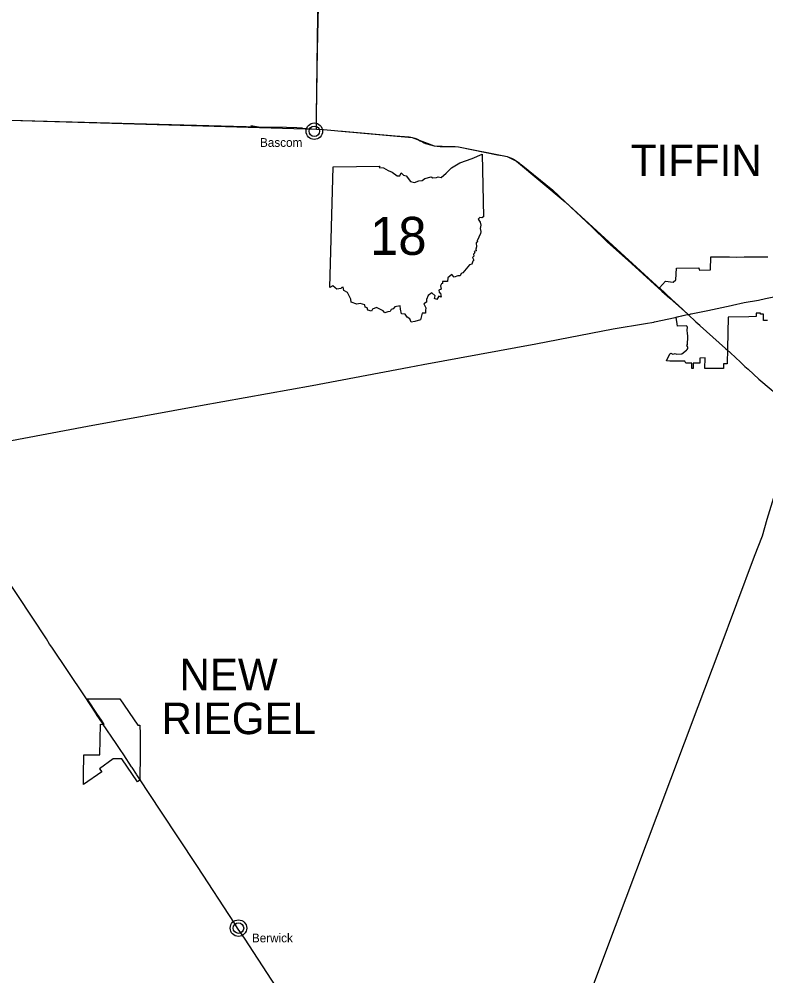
# Model space of a CAD drawing. Extents: x 0 to 882, y 0 to 440.
# Drawn here: x 198.3 to 287.2, y 123.7 to 237.6 of the extents above; entities that cross this region are included whole.
import ezdxf

# ---------------------------------------------------------------- set-up
doc = ezdxf.new("R2010")
doc.units = 0
for name, color, linetype in [('DV_X_Corp_Line', 7, 'Continuous'), ('GM_X_Corporation_Text', 7, 'Continuous'), ('GM_X_State_Route', 7, 'Continuous'), ('GM_X_US_Route', 7, 'Continuous'), ('PV_P_Text', 7, 'Continuous'), ('RD_P_Fence', 7, 'Continuous')]:
    doc.layers.add(name, color=color, linetype=linetype)

msp = doc.modelspace()

# ---------------------------------------------------------------- linework, layer by layer
at = {"layer": 'DV_X_Corp_Line'}
msp.add_lwpolyline([(287.43, 201.7), (286.94, 201.72), (286.95, 202.46), (286.58, 202.47), (286.58, 202.57), (286.46, 202.58), (286.08, 202.59), (286.07, 202.17), (285.19, 202.15), (282.76, 202.12), (282.67, 198.36), (282.62, 196.55), (282.2, 196.55), (282.19, 196), (281.61, 196), (279.98, 195.99), (280, 197.25), (279.37, 197.24), (279.37, 196.63), (278.59, 196.63), (278.59, 195.98), (278.44, 195.98), (278.44, 196.63), (277.82, 196.63), (277.7, 196.63), (277.6, 196.85), (275.8, 196.86), (275.39, 196.92), (275.81, 197.74), (275.93, 197.81), (276.17, 197.69), (276.3, 197.73), (276.43, 197.77), (276.59, 197.72), (277.24, 197.76), (277.79, 198.17), (277.86, 198.27), (277.94, 198.36), (277.96, 198.48), (277.9, 198.6), (277.84, 198.72), (277.89, 198.86), (277.93, 199.76), (277.93, 199.93), (277.9, 200.12), (277.87, 200.61), (277.9, 200.87), (277.88, 200.98), (277.82, 201.05), (277.79, 201.07), (276.73, 201.03), (276.55, 202.11), (277.71, 202.37), (277.97, 202.42), (276.84, 203.5), (276.04, 204.23), (274.57, 205.58), (275.3, 206.41), (276.18, 206.27), (276.5, 206.54), (276.58, 207.93), (279.25, 207.98), (279.24, 207.95), (279.34, 207.72), (280.65, 207.75), (280.69, 209.27), (282.91, 209.28), (283.76, 209.26), (284.65, 209.27), (286.52, 209.28), (287.46, 209.28)], dxfattribs=at)
msp.add_lwpolyline([(207.67, 154.81), (206.44, 156.66), (210.3, 156.68), (212.44, 153.54), (212.69, 153.52), (212.75, 152.47), (212.73, 150.02), (212.71, 147.2), (212.73, 147.02), (212.41, 146.81), (210.56, 149.53), (209.54, 149.52), (207.91, 148.35), (208.17, 148), (206, 146.49), (206, 147.57), (206.01, 150.02), (207.93, 150.02), (208, 153.65), (208.43, 153.63), (208.13, 154.12)], close=True, dxfattribs=at)
for centre, radius in [((233.47, 224.24), 0.982), ((233.47, 224.24), 0.623), ((224.44, 129.38), 0.982), ((224.44, 129.38), 0.623)]:
    msp.add_circle(centre, radius, dxfattribs=at)
at = {"layer": 'GM_X_State_Route'}
msp.add_line((187.98, 225.8), (226.83, 224.77), dxfattribs=at)
for points in [[(233.74, 226.08), (233.86, 233.93), (234.04, 242.59), (234.11, 245.45), (234.13, 247.53), (234.16, 248.62), (234.04, 250.01), (233.95, 252.28), (234.04, 255.38), (234.27, 261.27)], [(233.72, 224.5), (233.73, 225.08), (233.73, 225.7), (233.74, 226.08)], [(225.92, 224.91), (226.83, 224.77), (230.14, 224.73), (231.38, 224.68), (231.6, 224.66), (231.6, 224.66)], [(231.6, 224.66), (232, 224.63)], [(232, 224.63), (232.07, 224.62), (232.62, 224.58), (233.17, 224.54), (233.72, 224.5), (234.58, 224.43), (235.02, 224.4), (235.43, 224.37), (235.86, 224.34), (235.89, 224.34), (236.29, 224.3), (236.82, 224.26), (237.28, 224.22), (240, 223.98), (240.84, 223.9)], [(240.84, 223.9), (240.84, 223.9), (243.08, 223.71)], [(243.08, 223.71), (244.78, 223.56), (244.95, 223.53), (245.12, 223.51), (245.44, 223.41), (245.74, 223.28), (246.07, 223.1), (246.34, 222.96), (246.57, 222.87), (246.72, 222.8), (246.87, 222.73), (247.73, 222.52), (248.47, 222.43), (249.72, 222.41), (250.06, 222.43), (250.23, 222.42), (250.64, 222.39), (253.94, 221.7), (255.3, 221.45)], [(255.3, 221.45), (255.33, 221.44), (256.07, 221.31), (256.42, 221.22), (256.7, 221.11), (256.93, 221.03), (257.25, 220.87), (257.55, 220.68), (257.82, 220.5), (257.88, 220.45), (258.09, 220.27), (261.86, 217.24), (263.34, 215.85)], [(263.34, 215.85), (266.52, 212.87), (268.38, 211.05), (271.25, 208.48), (274.86, 205.21)], [(274.86, 205.21), (275.82, 204.35), (275.83, 204.34)], [(283.25, 203.53), (283.25, 203.53), (284.65, 203.84), (286.35, 204.13), (287.21, 204.31), (288.2, 204.52), (288.95, 204.68), (289.98, 204.91), (291.86, 205.34), (292, 205.36)], [(275.83, 204.34), (277.19, 203.12)], [(277.19, 203.12), (277.97, 202.42)], [(278.36, 202.5), (280.34, 202.89), (283.12, 203.5)], [(283.12, 203.5), (283.12, 203.5), (283.25, 203.53)], [(277.97, 202.42), (277.97, 202.42), (278.23, 202.47)], [(278.23, 202.47), (278.32, 202.49), (278.36, 202.5)], [(207.52, 154.85), (206.1, 157.04), (202.21, 162.84), (201.94, 163.2), (201.57, 163.82), (193.1, 176.61), (187.04, 185.47)], [(285.9, 173.66), (286.82, 176.09), (287.41, 178.05), (288.8, 182.71)], [(269.35, 129.63), (274.28, 142.8), (279.19, 155.78), (281.69, 162.37), (285.9, 173.66)], [(208.25, 153.77), (207.54, 154.82), (207.52, 154.85)], [(211.72, 148.57), (210.78, 150), (210.37, 150.63), (209.89, 151.34), (208.27, 153.73), (208.25, 153.77)], [(212.3, 147.69), (211.77, 148.5), (211.72, 148.57)], [(212.66, 147.14), (212.35, 147.62), (212.3, 147.69)], [(246.64, 96.86), (245.65, 97.52), (241.61, 103.4), (237.16, 110.07), (232.76, 116.59), (228.43, 123.2), (225.14, 128.19), (224.68, 128.87), (224.33, 129.39), (223.95, 129.96), (219.55, 136.71), (219.48, 136.82), (215.2, 143.29), (212.66, 147.14)], [(254.33, 100.7), (256.44, 103.39), (258.23, 105.6), (259.68, 107.49), (260.38, 108.5), (260.76, 109.14), (261.29, 110), (262.29, 111.6), (262.93, 112.69), (263.52, 114.12), (264.28, 116.06), (265.51, 119.32), (266.87, 123.06), (269.35, 129.63)]]:
    msp.add_lwpolyline(points, dxfattribs=at)
at = {"layer": 'GM_X_US_Route'}
for points in [[(273.96, 201.54), (276.42, 202.08)], [(276.42, 202.08), (276.55, 202.11), (276.68, 202.14)], [(276.68, 202.14), (277.71, 202.37), (277.71, 202.37)], [(277.71, 202.37), (277.97, 202.42)], [(277.97, 202.42), (278.89, 201.57)], [(187.04, 185.47), (206.46, 189.14), (219.92, 191.59), (233.2, 193.98), (244.76, 196.14), (246.45, 196.49), (259.84, 198.95), (269.07, 200.7), (272.92, 201.35), (273.91, 201.53), (273.96, 201.54)], [(278.89, 201.57), (279.36, 201.14)], [(279.36, 201.14), (279.42, 201.08), (282.44, 198.38)], [(282.44, 198.38), (282.64, 198.2), (283.03, 197.86), (284.2, 196.77)], [(284.2, 196.77), (284.21, 196.76), (284.39, 196.59)], [(284.39, 196.59), (284.39, 196.59), (284.66, 196.33), (284.75, 196.25)], [(284.75, 196.25), (285.12, 195.91), (285.78, 195.31), (286.39, 194.74), (287.86, 193.49), (288.42, 193.01), (289.75, 192.02), (290.82, 191.38), (291.41, 191.06)]]:
    msp.add_lwpolyline(points, dxfattribs=at)
at = {"layer": 'PV_P_Text'}
msp.add_line((235.3, 205.63), (235.7, 219.99), dxfattribs=at)
msp.add_line((235.3, 205.63), (235.7, 219.99), dxfattribs=at)
for points in [[(235.7, 219.99), (241.28, 220.08), (241.19, 219.91), (241.71, 219.87), (242.27, 219.57), (242.74, 219.37), (243.32, 218.92), (243.67, 218.92), (243.81, 219.29), (244.08, 219.01), (244.39, 218.95), (244.94, 218.27), (245.39, 218.12), (245.92, 218.35), (246.32, 218.39), (246.62, 218.63), (247.38, 218.82), (247.6, 218.7), (248, 218.73), (248.2, 218.82), (248.56, 218.74), (249.18, 219.26), (249.82, 219.88), (250.8, 220.46), (252.27, 221.01), (253.44, 221.5), (253.6, 214.05)], [(235.7, 219.99), (241.28, 220.08), (241.19, 219.91), (241.71, 219.87), (242.27, 219.57), (242.74, 219.37), (243.32, 218.92), (243.67, 218.92), (243.81, 219.29), (244.08, 219.01), (244.39, 218.95), (244.94, 218.27), (245.39, 218.12), (245.92, 218.35), (246.32, 218.39), (246.62, 218.63), (247.38, 218.82), (247.6, 218.7), (248, 218.73), (248.2, 218.82), (248.56, 218.74), (249.18, 219.26), (249.82, 219.88), (250.8, 220.46), (252.27, 221.01), (253.44, 221.5), (253.6, 214.05)], [(253.6, 214.05), (253.43, 213.94), (253.16, 213.99), (252.98, 213.78), (253.21, 213.43), (253.31, 213.07), (253.22, 212.66), (253.31, 212.32), (253.25, 212.04), (253.08, 211.76), (253.02, 211.5), (252.88, 211.22), (252.89, 211.06), (252.76, 210.94), (252.78, 210.47), (252.71, 210.21), (252.74, 209.99), (252.51, 209.93), (252.57, 209.75), (252.42, 209.61), (252.45, 209.36), (252.3, 209.2), (252.45, 208.89), (252.33, 208.79), (252.22, 208.41), (251.94, 208.33), (251.37, 207.64), (251.17, 207.38), (250.95, 207.31), (250.82, 207.04), (250.55, 207.04), (250.13, 206.85), (249.86, 207.17), (249.38, 206.79), (249.33, 206.34), (248.73, 206.35), (248.75, 206.13), (248.62, 206.06), (248.5, 205.83), (248.57, 205.43), (248.29, 205.33), (248.32, 205.09), (248.5, 204.95), (248.58, 204.5), (248.28, 204.59), (248.04, 204.22), (247.79, 204.31), (247.87, 204.63), (247.45, 205.01), (247.04, 204.7), (246.84, 204.21), (246.83, 203.88), (246.53, 203.68), (246.73, 203.21), (246.69, 202.89), (246.7, 202.59), (246.32, 202.6), (246.1, 201.77)], [(253.6, 214.05), (253.43, 213.94), (253.16, 213.99), (252.98, 213.78), (253.21, 213.43), (253.31, 213.07), (253.22, 212.66), (253.31, 212.32), (253.25, 212.04), (253.08, 211.76), (253.02, 211.5), (252.88, 211.22), (252.89, 211.06), (252.76, 210.94), (252.78, 210.47), (252.71, 210.21), (252.74, 209.99), (252.51, 209.93), (252.57, 209.75), (252.42, 209.61), (252.45, 209.36), (252.3, 209.2), (252.45, 208.89), (252.33, 208.79), (252.22, 208.41), (251.94, 208.33), (251.37, 207.64), (251.17, 207.38), (250.95, 207.31), (250.82, 207.04), (250.55, 207.04), (250.13, 206.85), (249.86, 207.17), (249.38, 206.79), (249.33, 206.34), (248.73, 206.35), (248.75, 206.13), (248.62, 206.06), (248.5, 205.83), (248.57, 205.43), (248.29, 205.33), (248.32, 205.09), (248.5, 204.95), (248.58, 204.5), (248.28, 204.59), (248.04, 204.22), (247.79, 204.31), (247.87, 204.63), (247.45, 205.01), (247.04, 204.7), (246.84, 204.21), (246.83, 203.88), (246.53, 203.68), (246.73, 203.21), (246.69, 202.89), (246.7, 202.59), (246.32, 202.6), (246.1, 201.77)], [(246.1, 201.77), (245.45, 201.61), (244.99, 201.52), (244.83, 201.89), (244.51, 202.09), (244.3, 202.47), (243.84, 202.52), (243.73, 203.04), (243.68, 203.46), (243.04, 203.35), (242.87, 203.1), (242.64, 203.03), (242.51, 202.77), (242.21, 202.75), (241.88, 202.63), (241.66, 202.88), (241.12, 203.14), (240.88, 203.27), (240.38, 203.06), (240.27, 202.82), (239.86, 202.93), (239.77, 203.2), (239.53, 203.28), (239.47, 203.56), (238.95, 203.72), (238.55, 203.66), (237.85, 203.89), (237.81, 204.26), (237.57, 204.72), (237.44, 205.04), (237, 205.28), (236.91, 205.66), (236.76, 205.65), (236.63, 205.5), (236.14, 205.43), (235.94, 205.58), (235.67, 205.84), (235.3, 205.63)], [(246.1, 201.77), (245.45, 201.61), (244.99, 201.52), (244.83, 201.89), (244.51, 202.09), (244.3, 202.47), (243.84, 202.52), (243.73, 203.04), (243.68, 203.46), (243.04, 203.35), (242.87, 203.1), (242.64, 203.03), (242.51, 202.77), (242.21, 202.75), (241.88, 202.63), (241.66, 202.88), (241.12, 203.14), (240.88, 203.27), (240.38, 203.06), (240.27, 202.82), (239.86, 202.93), (239.77, 203.2), (239.53, 203.28), (239.47, 203.56), (238.95, 203.72), (238.55, 203.66), (237.85, 203.89), (237.81, 204.26), (237.57, 204.72), (237.44, 205.04), (237, 205.28), (236.91, 205.66), (236.76, 205.65), (236.63, 205.5), (236.14, 205.43), (235.94, 205.58), (235.67, 205.84), (235.3, 205.63)]]:
    msp.add_lwpolyline(points, dxfattribs=at)
at = {"layer": 'RD_P_Fence'}
for points in [[(233.74, 226.08), (234.04, 250.01), (234.84, 275.26), (234.84, 285.96), (234.98, 304.67)], [(164.21, 228.05), (170.34, 227.07), (172.66, 226.87), (186.31, 225.87), (233.72, 224.5)], [(236.29, 224.3), (236.29, 224.3), (245.12, 223.51), (247.73, 222.52), (250.64, 222.39), (256.42, 221.22), (257.55, 220.68), (263.34, 215.85), (277.97, 202.42)]]:
    msp.add_lwpolyline(points, dxfattribs=at)

# ---------------------------------------------------------------- texts
at = {"layer": 'DV_X_Corp_Line'}
for s, p in [('Bascom', (227.01, 222.38)), ('Berwick', (226.04, 127.69))]:
    msp.add_text(s, height=1.042, rotation=0, dxfattribs=at).set_placement(p)
at = {"layer": 'GM_X_Corporation_Text'}
for s, p in [('TIFFIN', (271.15, 218.91)), ('NEW', (217.41, 157.69)), ('RIEGEL', (215.28, 152.47))]:
    msp.add_text(s, height=3.75, rotation=0, dxfattribs=at).set_placement(p)
at = {"layer": 'PV_P_Text'}
msp.add_text('18', height=4.528, dxfattribs=at).set_placement((240.1, 209.52))

doc.saveas('drawing.dxf')
